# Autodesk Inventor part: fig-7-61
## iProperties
Shininess: 64.0
Length Units: 11269
Angle Units: 11279
Time Units: 11290
Mass Units: 11283
Length Display Precision: 3
Angle Display Precision: 2
Compacted: True
Part Number: fig-7-61
Document SubType Name: Modeling
Created: 2003-08
Designer: Owner
Manufacturer: Standard
Standards Organization: Custom
Density: 0.0
Volumn: 0.0
Area: 0.0
PropertySet Name: Model Information
Control State: 0
Master: False
Checked Out: False
Author: Owner
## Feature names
1. Split6
2. Split7
